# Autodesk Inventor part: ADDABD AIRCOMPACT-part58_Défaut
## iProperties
Shininess: 64.0
Length Units: 11269
Angle Units: 11279
Time Units: 11290
Mass Units: 11283
Length Display Precision: 3
Angle Display Precision: 2
Compacted: True
Part Number: ADDABD AIRCOMPACT-part58_Défaut
Document SubType Name: Modeling
Created: 2006-01
Material: Par défaut
Designer: riri
Density: 0.0
Volumn: 0.0
Area: 0.0
PropertySet Name: Model Information
Control State: 0
Master: False
Checked Out: False
Author: riri
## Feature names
1. Base1
